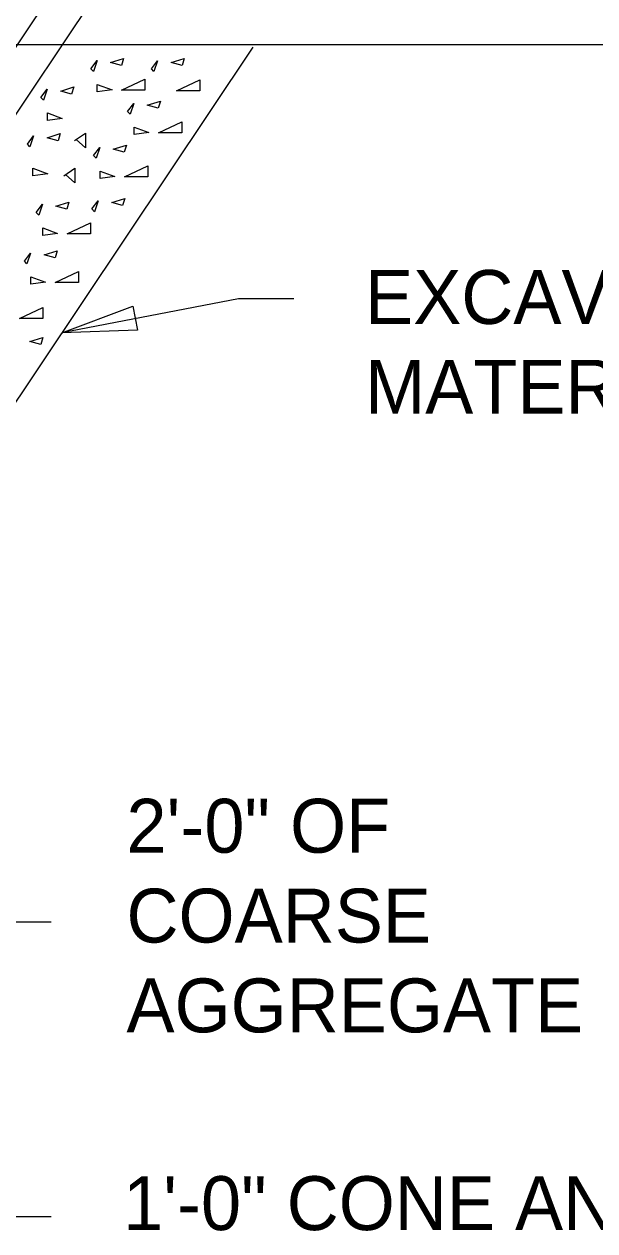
# Model space of a CAD drawing. Extents: x 1299104.8 to 1299141.6, y 239639.8 to 239661.8.
# Drawn here: x 1299116.944 to 1299118.214, y 239644.477 to 239647.164 of the extents above; entities that cross this region are included whole.
import ezdxf

# ---------------------------------------------------------------- set-up
doc = ezdxf.new("R2010")
doc.units = 0
doc.layers.add('DIM TXT', color=7, linetype='Continuous')

msp = doc.modelspace()

# ---------------------------------------------------------------- linework, layer by layer
at = {"layer": 'DIM TXT'}
for p, q in [((1299117.2976, 239647.6699), (1299115.8601, 239645.522)), ((1299117.365, 239647.6209), (1299115.9275, 239645.4731)), ((1299114.989, 239647.1184), (1299123.7976, 239647.1184)), ((1299117.4533, 239647.1125), (1299115.9299, 239644.8364)), ((1299117.0922, 239647.0642), (1299117.1061, 239647.0825)), ((1299117.1061, 239647.0825), (1299117.098, 239647.0582)), ((1299117.1362, 239647.0783), (1299117.1651, 239647.0875)), ((1299117.1605, 239647.0716), (1299117.1362, 239647.0783)), ((1299117.1651, 239647.0875), (1299117.1605, 239647.0716)), ((1299117.2271, 239647.064), (1299117.2409, 239647.0823)), ((1299117.2409, 239647.0823), (1299117.2328, 239647.058)), ((1299117.271, 239647.0781), (1299117.3, 239647.0873)), ((1299117.2953, 239647.0714), (1299117.271, 239647.0781)), ((1299117.3, 239647.0873), (1299117.2953, 239647.0714)), ((1299117.098, 239647.0582), (1299117.0922, 239647.0642)), ((1299117.1607, 239647.0167), (1299117.2129, 239647.0414)), ((1299117.2129, 239647.0414), (1299117.2129, 239647.0167)), ((1299117.2328, 239647.058), (1299117.2271, 239647.064)), ((1299117.2827, 239647.0153), (1299117.3349, 239647.04)), ((1299117.3349, 239647.04), (1299117.3349, 239647.0153)), ((1299116.9814, 239647.0007), (1299116.9953, 239647.0189)), ((1299116.9953, 239647.0189), (1299116.9872, 239646.9946)), ((1299117.0254, 239647.0148), (1299117.0543, 239647.024)), ((1299117.0497, 239647.0081), (1299117.0254, 239647.0148)), ((1299117.0543, 239647.024), (1299117.0497, 239647.0081)), ((1299117.1066, 239647.0297), (1299117.1397, 239647.0174)), ((1299117.1066, 239647.013), (1299117.1066, 239647.0297)), ((1299117.1397, 239647.0174), (1299117.1066, 239647.013)), ((1299117.2129, 239647.0167), (1299117.1607, 239647.0167)), ((1299117.3349, 239647.0153), (1299117.2827, 239647.0153)), ((1299116.9872, 239646.9946), (1299116.9814, 239647.0007)), ((1299117.1742, 239646.969), (1299117.1881, 239646.9873)), ((1299117.1881, 239646.9873), (1299117.18, 239646.963)), ((1299117.2181, 239646.9831), (1299117.2471, 239646.9923)), ((1299117.2471, 239646.9923), (1299117.2424, 239646.9764)), ((1299116.9957, 239646.9495), (1299116.9957, 239646.9662)), ((1299116.9957, 239646.9662), (1299117.0289, 239646.9538)), ((1299117.18, 239646.963), (1299117.1742, 239646.969)), ((1299117.2424, 239646.9764), (1299117.2181, 239646.9831)), ((1299117.0289, 239646.9538), (1299116.9957, 239646.9495)), ((1299117.1885, 239646.9178), (1299117.1885, 239646.9345)), ((1299117.1885, 239646.9345), (1299117.2216, 239646.9222)), ((1299117.2427, 239646.9214), (1299117.2949, 239646.9461)), ((1299117.2949, 239646.9461), (1299117.2949, 239646.9214)), ((1299116.9511, 239646.8968), (1299116.965, 239646.915)), ((1299116.965, 239646.915), (1299116.9569, 239646.8907)), ((1299116.9951, 239646.9108), (1299117.024, 239646.9201)), ((1299117.0194, 239646.9041), (1299116.9951, 239646.9108)), ((1299117.024, 239646.9201), (1299117.0194, 239646.9041)), ((1299117.0562, 239646.9044), (1299117.0803, 239646.9211)), ((1299117.0803, 239646.8884), (1299117.0599, 239646.907)), ((1299117.0803, 239646.9211), (1299117.0803, 239646.8884)), ((1299117.2216, 239646.9222), (1299117.1885, 239646.9178)), ((1299117.2949, 239646.9214), (1299117.2427, 239646.9214)), ((1299116.9569, 239646.8907), (1299116.9511, 239646.8968)), ((1299117.0985, 239646.8712), (1299117.1123, 239646.8894)), ((1299117.1123, 239646.8894), (1299117.1042, 239646.8651)), ((1299117.1424, 239646.8852), (1299117.1714, 239646.8945)), ((1299117.1667, 239646.8785), (1299117.1424, 239646.8852)), ((1299117.1714, 239646.8945), (1299117.1667, 239646.8785)), ((1299117.1042, 239646.8651), (1299117.0985, 239646.8712)), ((1299116.9632, 239646.8263), (1299116.9632, 239646.843)), ((1299116.9632, 239646.843), (1299116.9963, 239646.8306)), ((1299116.9963, 239646.8306), (1299116.9632, 239646.8263)), ((1299117.0324, 239646.8263), (1299117.0565, 239646.843)), ((1299117.0565, 239646.8103), (1299117.0361, 239646.8289)), ((1299117.0565, 239646.843), (1299117.0565, 239646.8103)), ((1299117.1128, 239646.8367), (1299117.1459, 239646.8243)), ((1299117.1128, 239646.82), (1299117.1128, 239646.8367)), ((1299117.167, 239646.8236), (1299117.2192, 239646.8483)), ((1299117.2192, 239646.8483), (1299117.2192, 239646.8236)), ((1299117.1459, 239646.8243), (1299117.1128, 239646.82)), ((1299117.2192, 239646.8236), (1299117.167, 239646.8236)), ((1299117.1388, 239646.7663), (1299117.1678, 239646.7756)), ((1299117.1678, 239646.7756), (1299117.1631, 239646.7596)), ((1299116.9708, 239646.7444), (1299116.9847, 239646.7627)), ((1299116.9766, 239646.7384), (1299116.9708, 239646.7444)), ((1299116.9847, 239646.7627), (1299116.9766, 239646.7384)), ((1299117.0148, 239646.7585), (1299117.0437, 239646.7677)), ((1299117.0391, 239646.7518), (1299117.0148, 239646.7585)), ((1299117.0437, 239646.7677), (1299117.0391, 239646.7518)), ((1299117.0949, 239646.7523), (1299117.1087, 239646.7705)), ((1299117.1006, 239646.7462), (1299117.0949, 239646.7523)), ((1299117.1087, 239646.7705), (1299117.1006, 239646.7462)), ((1299117.1631, 239646.7596), (1299117.1388, 239646.7663)), ((1299117.0394, 239646.6969), (1299117.0915, 239646.7216)), ((1299117.0915, 239646.7216), (1299117.0915, 239646.6969)), ((1299116.9852, 239646.6932), (1299116.9852, 239646.71)), ((1299116.9852, 239646.71), (1299117.0183, 239646.6976)), ((1299117.0183, 239646.6976), (1299116.9852, 239646.6932)), ((1299117.0915, 239646.6969), (1299117.0394, 239646.6969)), ((1299116.9444, 239646.636), (1299116.9583, 239646.6542)), ((1299116.9583, 239646.6542), (1299116.9502, 239646.6299)), ((1299116.9884, 239646.6501), (1299117.0173, 239646.6593)), ((1299117.0127, 239646.6434), (1299116.9884, 239646.6501)), ((1299117.0173, 239646.6593), (1299117.0127, 239646.6434)), ((1299116.9502, 239646.6299), (1299116.9444, 239646.636)), ((1299117.0129, 239646.5884), (1299117.0651, 239646.6131)), ((1299117.0651, 239646.6131), (1299117.0651, 239646.5884)), ((1299116.9587, 239646.5848), (1299116.9587, 239646.6015)), ((1299116.9587, 239646.6015), (1299116.9918, 239646.5891)), ((1299116.9918, 239646.5891), (1299116.9587, 239646.5848)), ((1299117.0651, 239646.5884), (1299117.0129, 239646.5884)), ((1299116.9334, 239646.5082), (1299116.9855, 239646.5329)), ((1299116.9855, 239646.5329), (1299116.9855, 239646.5082)), ((1299117.4211, 239646.5521), (1299117.0275, 239646.4763)), ((1299117.5441, 239646.5521), (1299117.4211, 239646.5521)), ((1299116.9855, 239646.5082), (1299116.9334, 239646.5082)), ((1299116.9566, 239646.4572), (1299116.9856, 239646.4664)), ((1299116.9809, 239646.4505), (1299116.9566, 239646.4572)), ((1299116.9856, 239646.4664), (1299116.9809, 239646.4505)), ((1299117.0041, 239645.1641), (1299116.8112, 239645.1641)), ((1299117.0041, 239644.508), (1299116.8112, 239644.508))]:
    msp.add_line(p, q, dxfattribs=at)
msp.add_lwpolyline([(1299117.1858, 239646.5356), (1299117.1964, 239646.4823), (1299117.0275, 239646.4763)], close=True, dxfattribs=at)

# ---------------------------------------------------------------- texts
for s, p in [('EXCAVATED ', (1299117.7029, 239646.4963)), ('MATERIAL', (1299117.7029, 239646.2963)), ('2\'-0" OF ', (1299117.1717, 239645.319)), ('COARSE ', (1299117.1717, 239645.119)), ('AGGREGATE', (1299117.1717, 239644.919)), ('1\'-0" CONE ANCHOR', (1299117.1642, 239644.4788))]:
    msp.add_text(s, height=0.12, dxfattribs=at).set_placement(p)

doc.saveas('drawing.dxf')
